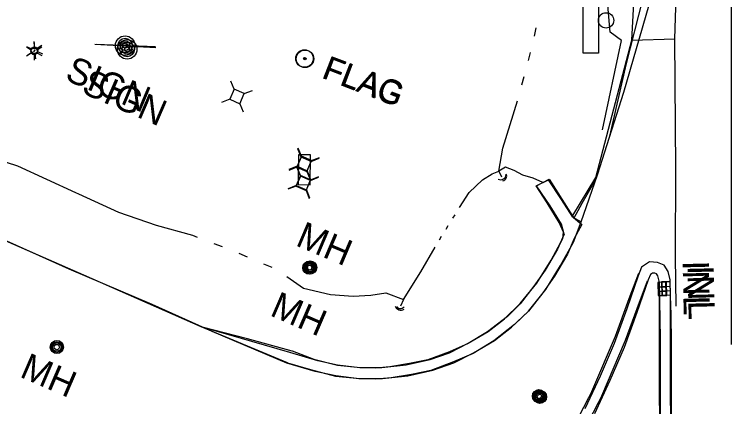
# Model space of a CAD drawing. Extents: x 588843 to 2552415, y 180129 to 269402.
# Drawn here: x 593696.8 to 593860.8, y 185673.4 to 185762.9 of the extents above; entities that cross this region are included whole.
import ezdxf

# ---------------------------------------------------------------- set-up
doc = ezdxf.new("R2010")
doc.units = 0
for name, color, linetype in [('Default', 7, 'Continuous'), ('E_AREA', 7, 'Continuous'), ('E_DRN', 7, 'Continuous'), ('E_DRN_Text', 7, 'Continuous'), ('E_LTG', 7, 'Continuous'), ('E_MISCPROP', 7, 'Continuous'), ('E_RDWY', 7, 'Continuous'), ('E_RDWY_AsphConc', 7, 'Continuous'), ('E_RDWY_C_and_G', 7, 'Continuous'), ('E_RDWY_Gravel', 7, 'Continuous'), ('E_RDWY_PavtEdge', 7, 'Continuous'), ('E_SGN', 7, 'Continuous'), ('E_SGN_Text', 7, 'Continuous'), ('E_UTL_AG_Bold', 7, 'Continuous'), ('E_UTL_MH', 7, 'Continuous'), ('E_UTL_MH_Text', 7, 'Continuous'), ('E_WTR_P', 7, 'Continuous')]:
    doc.layers.add(name, color=color, linetype=linetype)

# ---------------------------------------------------------------- blocks, each defined once
blk = doc.blocks.new('LPOL')
at = {"layer": 'Default'}
for p, q in [((-0.75, 1.3), (-2, 3.46)), ((0.75, 1.3), (2, 3.46)), ((-4, 0), (-1.5, 0)), ((1.5, 0), (4, 0)), ((-2, -3.46), (-0.75, -1.3)), ((2, -3.46), (0.75, -1.3))]:
    blk.add_line(p, q, dxfattribs=at)
for radius in [1.5, 1.5, 1.5, 0.125]:
    blk.add_circle((0, 0), radius, dxfattribs=at)
blk = doc.blocks.new('POLE')
at = {"layer": 'Default'}
for radius in [4.46, 3.35, 2.23, 1.12]:
    blk.add_circle((0, 0), radius, dxfattribs=at)
blk = doc.blocks.new('SIGN')
at = {"layer": 'Default'}
blk.add_text('SIGN', height=12, dxfattribs=at).set_placement((-18.55, -6))
blk = doc.blocks.new('PED')
at = {"layer": 'Default'}
for p, q in [((-2.5, 2.5), (-5.33, 5.33)), ((2.5, 2.5), (5.33, 5.33)), ((-2.5, -2.5), (-5.33, -5.33)), ((2.5, -2.5), (5.33, -5.33))]:
    blk.add_line(p, q, dxfattribs=at)
blk.add_lwpolyline([(-2.5, -2.5), (2.5, -2.5), (2.5, 2.5), (-2.5, 2.5)], close=True, dxfattribs=at)
blk = doc.blocks.new('MHO')
at = {"layer": 'Default'}
for centre, radius in [((0.08, -0.12), 3), ((0.08, -0.12), 2.43), ((0.07, -0.15), 1.94), ((0.02, -0.16), 1.21)]:
    blk.add_circle(centre, radius, dxfattribs=at)
blk = doc.blocks.new('MHT')
at = {"layer": 'E_UTL_MH_Text'}
blk.add_text('MH', height=12, dxfattribs=at).set_placement((-9.81, -6))
blk = doc.blocks.new('FPOL')
at = {"layer": 'Default'}
for radius in [4, 0.5]:
    blk.add_circle((0, 0), radius, dxfattribs=at)
blk.add_text('FLAG', height=10.8, dxfattribs=at).set_placement((10, -5.4))
blk = doc.blocks.new('INLO')
at = {"layer": 'E_DRN'}
for p, q in [((2, -4), (2, 0)), ((4, -4), (4, 0)), ((6, -2), (0, -2))]:
    blk.add_line(p, q, dxfattribs=at)
blk.add_lwpolyline([(0, -4), (6, -4), (6, 0), (0, 0), (0, -4)], close=True, dxfattribs=at)
blk = doc.blocks.new('INLT_24')
at = {"layer": 'E_DRN_Text'}
blk.add_text('INL', height=12, dxfattribs=at).set_placement((-11.03, -6))
blk = doc.blocks.new('CULV2')
at = {"layer": 'E_DRN'}
blk.add_arc((19.7, 14.8), 24.6, 216.8699, 323.1301, dxfattribs=at)
blk = doc.blocks.new('SGN_1')
at = {"layer": 'Default'}
blk.add_lwpolyline([(-3.5, -15), (-10.5, -15), (-10.5, 15), (-3.5, 15)], close=True, dxfattribs=at)
blk.add_circle((0, 0), 3.5, dxfattribs=at)
blk = doc.blocks.new('CULV2_4')
at = {"layer": 'E_DRN'}
blk.add_arc((64.6, 48.4), 80.7, 216.8699, 323.1301, dxfattribs=at)
blk = doc.blocks.new('INLO_3')
at = {"layer": 'E_DRN'}
for p, q in [((6.6, -13.1), (6.6, 0)), ((13.1, -13.1), (13.1, 0)), ((19.7, -6.6), (0, -6.6))]:
    blk.add_line(p, q, dxfattribs=at)
blk.add_lwpolyline([(0, -13.1), (19.7, -13.1), (19.7, 0), (0, 0)], close=True, dxfattribs=at)
blk = doc.blocks.new('INLT_44')
at = {"layer": 'E_DRN_Text'}
blk.add_text('INL', height=39.37, dxfattribs=at).set_placement((-36.2, -19.7))
blk = doc.blocks.new('MHO_3')
at = {"layer": 'E_UTL_MH'}
for centre, radius in [((0.3, -0.4), 9.84), ((0.3, -0.4), 7.98), ((0.2, -0.5), 6.35), ((0.1, -0.5), 3.97)]:
    blk.add_circle(centre, radius, dxfattribs=at)
blk = doc.blocks.new('PED_3')
at = {"layer": 'E_UTL_AG_Bold'}
for p, q in [((-8.2, 8.2), (-17.5, 17.5)), ((8.2, 8.2), (17.5, 17.5)), ((-8.2, -8.2), (-17.5, -17.5)), ((8.2, -8.2), (17.5, -17.5))]:
    blk.add_line(p, q, dxfattribs=at)
blk.add_lwpolyline([(-8.2, -8.2), (8.2, -8.2), (8.2, 8.2), (-8.2, 8.2)], close=True, dxfattribs=at)
blk = doc.blocks.new('LPOL_4')
at = {"layer": 'E_LTG'}
for p, q in [((-2.5, 4.3), (-6.6, 11.4)), ((2.5, 4.3), (6.6, 11.4)), ((-13.1, 0), (-4.9, 0)), ((4.9, 0), (13.1, 0)), ((-6.6, -11.4), (-2.5, -4.3)), ((6.6, -11.4), (2.5, -4.3))]:
    blk.add_line(p, q, dxfattribs=at)
for radius in [4.92, 4.92, 4.92, 0.41]:
    blk.add_circle((0, 0), radius, dxfattribs=at)
blk = doc.blocks.new('POLE_3')
at = {"layer": 'E_MISCPROP'}
for radius in [14.6, 11, 7.32, 3.66]:
    blk.add_circle((0, 0), radius, dxfattribs=at)
blk = doc.blocks.new('FPOL_2')
at = {"layer": 'E_MISCPROP'}
for radius in [13.1, 1.64]:
    blk.add_circle((0, 0), radius, dxfattribs=at)
blk.add_text('FLAG', height=35.43, dxfattribs=at).set_placement((32.8, -17.7))
blk = doc.blocks.new('SIGN_3')
at = {"layer": 'E_SGN'}
blk.add_text('SIGN', height=39.37, dxfattribs=at).set_placement((-56.1, -19.7))
blk = doc.blocks.new('MHT_1_1')
at = {"layer": 'E_UTL_MH'}
blk.add_text('MH', height=39.37, dxfattribs=at).set_placement((-32.2, -19.7))

msp = doc.modelspace()

# ---------------------------------------------------------------- linework, layer by layer
at = {"layer": 'E_AREA'}
msp.add_lwpolyline([(593764.45, 185724.01), (593764.53, 185730.85), (593761.77, 185730.88), (593761.68, 185724.05)], close=True, dxfattribs=at)
at = {"layer": 'E_RDWY'}
for points in [[(593759.1, 185683.31), (593742.04, 185690.53), (593728.3, 185696.69), (593709.33, 185704.73), (593695.77, 185710.83), (593682.84, 185716.47), (593670.2, 185721.87), (593658.17, 185727.03), (593647.4, 185731.86), (593631.92, 185738.54), (593621.67, 185743), (593610.57, 185747.71), (593598.94, 185752.59), (593585.45, 185758.54), (593573.64, 185763.64), (593561.33, 185768.89), (593544.91, 185776.17), (593525.62, 185787.49)], [(593759.23, 185683.39), (593739.55, 185691.58), (593712.69, 185703.4), (593684.94, 185715.45), (593651.85, 185729.61), (593625.47, 185740.91), (593596.7, 185753.38), (593563.11, 185767.85), (593537.55, 185779.12), (593525.28, 185784.5)], [(593824.44, 185716.62), (593826.41, 185715.58), (593830.12, 185726.28), (593836.13, 185745.12), (593841.89, 185765.08)], [(593822.49, 185712.74), (593821.85, 185714.99), (593819.27, 185719.19), (593816.17, 185723.77), (593819.09, 185725.3), (593823.93, 185717.6), (593824.62, 185716.54), (593826.52, 185714.96), (593824.78, 185711.76)]]:
    msp.add_lwpolyline(points, dxfattribs=at)
at = {"layer": 'E_RDWY_AsphConc'}
for points in [[(593837.95, 185757.04), (593839.67, 185789.55), (593841.84, 185838.91), (593843.28, 185888.97), (593844.22, 185921.24), (593844.22, 185921.24), (593844.83, 185937.64), (593844.83, 185937.64), (593846.87, 185985.61), (593846.87, 185985.61), (593846.9, 185986.19), (593846.9, 185986.19), (593847.86, 186002.92), (593847.86, 186002.92), (593849.8, 186035.84), (593849.8, 186035.84), (593849.89, 186037.26), (593849.89, 186037.26), (593852.73, 186084.79), (593853.52, 186097.05), (593853.52, 186097.05), (593855.43, 186124.4), (593855.43, 186124.4)], [(593824.49, 185717), (593829.72, 185725.66), (593837.95, 185757.04), (593847.81, 185757.3)], [(593848.12, 185696.34), (593847.9, 185707.68), (593848.04, 185727.75), (593847.81, 185757.3)]]:
    msp.add_lwpolyline(points, dxfattribs=at)
at = {"layer": 'E_RDWY_C_and_G'}
for points in [[(593760.34, 185686.11), (593765.28, 185684.2), (593770.66, 185682.82), (593775.96, 185682.27), (593780.78, 185682.27), (593786.34, 185682.9), (593791.83, 185684.14), (593796.26, 185685.64), (593800.52, 185687.87), (593805.13, 185690.54), (593808.84, 185693.44), (593812.46, 185696.9), (593816.26, 185701.53), (593819.5, 185706.83), (593822.22, 185711.78), (593822.31, 185713.22), (593821.35, 185715.39), (593818.57, 185719.91), (593816.06, 185723.79), (593818.93, 185725.13)], [(593824.44, 185716.62), (593821.72, 185720.91), (593818.93, 185725.13)], [(593759.23, 185683.39), (593764.51, 185681.81), (593770.22, 185680.35), (593775.83, 185679.77), (593780.93, 185679.77), (593786.76, 185680.43), (593792.5, 185681.73), (593797.24, 185683.34), (593801.73, 185685.68), (593806.53, 185688.46), (593810.47, 185691.54), (593814.3, 185695.2), (593818.3, 185700.08), (593821.66, 185705.57), (593824.6, 185710.93), (593826.41, 185715.58)], [(593824.78, 185711.76), (593823.23, 185708.14), (593820.26, 185703.13), (593817.58, 185699.37), (593814.3, 185695.19), (593811.16, 185692.09), (593806.43, 185688.41), (593801.7, 185685.52), (593797.2, 185683.56), (593792.03, 185681.65), (593787.58, 185680.72), (593782.96, 185679.95), (593779.42, 185679.65), (593775.59, 185679.72), (593770.3, 185680.39), (593765.59, 185681.38), (593759.07, 185683.29)], [(593822.49, 185712.74), (593821, 185709.28), (593818.16, 185704.49), (593815.58, 185700.87), (593812.43, 185696.86), (593809.51, 185693.98), (593805, 185690.47), (593800.54, 185687.75), (593796.27, 185685.88), (593791.34, 185684.06), (593787.12, 185683.18), (593782.64, 185682.44), (593779.34, 185682.15), (593775.77, 185682.22), (593770.71, 185682.86), (593766.2, 185683.81), (593759.77, 185685.69)], [(593846.84, 185669.38), (593846.76, 185677.79), (593846.8, 185698.58), (593846.71, 185702.32), (593846.24, 185704.19), (593845.32, 185705.67), (593843.83, 185706.28), (593841.99, 185706.42), (593840.16, 185705.18), (593839.38, 185703.21), (593836.78, 185695.67), (593833.88, 185687.81), (593830.68, 185680.34), (593827.19, 185672.86)], [(593846.76, 185697.53), (593846.93, 185689.06), (593846.95, 185664.12), (593846.94, 185653.04), (593846.28, 185651.51), (593845.16, 185650.27), (593843.9, 185649.34), (593842.62, 185648.72), (593840.87, 185648.28), (593827.3, 185652.15), (593823.42, 185653.26), (593822.24, 185653.8), (593820.79, 185655.02), (593820.26, 185656.61), (593819.9, 185658.3), (593820.18, 185660.06), (593824.69, 185668.82), (593828.15, 185675.47), (593828.79, 185676.8), (593834.19, 185689.48), (593837.34, 185698.09), (593839.55, 185703.83)], [(593844.34, 185669.38), (593844.26, 185677.79), (593844.3, 185698.56), (593844.22, 185701.98), (593843.91, 185703.21), (593843.62, 185703.67), (593843.25, 185703.82), (593842.67, 185703.86), (593842.2, 185703.54), (593841.72, 185702.34), (593839.13, 185694.83), (593836.2, 185686.89), (593832.96, 185679.32), (593829.43, 185671.76)], [(593844.17, 185701.71), (593844.43, 185689.03), (593844.45, 185664.12), (593844.44, 185653.56), (593844.15, 185652.88), (593843.48, 185652.13), (593842.6, 185651.49), (593841.76, 185651.08), (593840.92, 185650.87), (593827.99, 185654.55), (593824.29, 185655.61), (593823.58, 185655.93), (593822.94, 185656.48), (593822.67, 185657.27), (593822.44, 185658.36), (593822.59, 185659.27), (593826.92, 185667.67), (593830.37, 185674.32), (593831.08, 185675.82), (593836.51, 185688.56), (593839.68, 185697.21), (593841.55, 185702.08)]]:
    msp.add_lwpolyline(points, dxfattribs=at)
at = {"layer": 'E_RDWY_Gravel'}
msp.add_line((593759.77, 185685.69), (593740.08, 185691.41), dxfattribs=at)
for points in [[(593831.22, 185736.59), (593835.61, 185756.96), (593833.01, 185758.89), (593830.96, 185782.65), (593830.12, 185791.32), (593830.79, 185838.58), (593829.63, 185872.43), (593828.76, 185889.27)], [(593832.93, 185735.09), (593836.71, 185751.67), (593840.45, 185766.4), (593843.33, 185777.36), (593845.2, 185783.93), (593847.16, 185791.33)], [(593824.79, 185716.44), (593826.62, 185719.82), (593829.81, 185725.4)], [(593760.31, 185686.02), (593750.11, 185688.84), (593739.77, 185691.49)]]:
    msp.add_lwpolyline(points, dxfattribs=at)
at = {"layer": 'E_RDWY_PavtEdge'}
for points in [[(593847.81, 185757.3), (593848.76, 185788.45), (593849.81, 185838.52), (593850.55, 185888.9), (593851.07, 185921.17), (593851.07, 185921.17), (593851.53, 185937.39), (593851.53, 185937.39), (593853.26, 185984.29), (593853.26, 185984.29), (593853.32, 185985.9), (593853.32, 185985.9), (593854.89, 186023.96), (593854.89, 186023.96), (593855.46, 186035.86), (593855.46, 186035.86), (593855.74, 186040.82), (593855.74, 186040.82), (593858.37, 186084.45), (593858.37, 186084.45), (593859.08, 186096.87), (593859.08, 186096.87), (593860.55, 186123.99), (593860.55, 186123.99)], [(593860.7, 185687.52), (593860.77, 185701.49), (593860.73, 185757.58), (593860.74, 185788.64)]]:
    msp.add_lwpolyline(points, dxfattribs=at)
at = {"layer": 'E_SGN'}
msp.add_line((593715.24, 185756.14), (593729.17, 185755.39), dxfattribs=at)
msp.add_lwpolyline([(593715.5, 185756.09), (593729.08, 185755.61)], dxfattribs=at)
at = {"layer": 'E_WTR_P'}
for points in [[(593815.71, 185757.96), (593816.11, 185759.83)], [(593814.34, 185752.4), (593814.82, 185754.24)], [(593812.84, 185746.86), (593813.35, 185748.71)], [(593817.6, 185724.55), (593815.37, 185725.51), (593813.06, 185726.19), (593811.04, 185727.3), (593809.05, 185728.04), (593807.56, 185727.13), (593808.45, 185732.4), (593811.83, 185743.18)], [(593683.23, 185733.06), (593685.44, 185732.21), (593697.5, 185728.35), (593710.8, 185722.23)], [(593798.57, 185718.81), (593800.8, 185722.25), (593803.8, 185725.12), (593806, 185726.52), (593807.56, 185727.13), (593808.2, 185725.82)], [(593710.8, 185722.23), (593711.48, 185721.92), (593720.63, 185717.74), (593729.23, 185714.79), (593737.51, 185712.51), (593738.6, 185712.09)], [(593797.03, 185716.37), (593797.54, 185717.18)], [(593795.49, 185713.92), (593796, 185714.74)], [(593793.99, 185711.45), (593794.47, 185712.28)], [(593742.42, 185710.62), (593744.33, 185709.89)], [(593785.75, 185697.83), (593789.73, 185704.13), (593793.02, 185709.78)], [(593748.13, 185708.39), (593750.01, 185707.59)], [(593753.78, 185706), (593755.66, 185705.2)], [(593759.13, 185703.06), (593762.92, 185700.41), (593769.04, 185698.96), (593774.24, 185698.56), (593778.27, 185698.85), (593781.69, 185699.33), (593785.75, 185697.83), (593785.04, 185696.29)]]:
    msp.add_lwpolyline(points, dxfattribs=at)

# ---------------------------------------------------------------- block references
at = {"layer": 'E_DRN'}
for name, p, xscale, yscale, rotation in [('CULV2_4', (593807.43, 185725.28), 0.016407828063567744, 0.016407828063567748, 30.421582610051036), ('CULV2', (593808.48, 185724.93), 0.043553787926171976, 0.04355378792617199, 63.12337477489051), ('INLO', (593845.9, 185701.75), 0.5, 0.4999999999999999, -88.75564168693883), ('INLO_3', (593846.72, 185701.88), 0.1524003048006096, 0.1524003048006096, -88.62500351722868), ('CULV2_4', (593783.88, 185696.31), 0.016475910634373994, 0.016475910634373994, -19.028589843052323), ('CULV2', (593784.16, 185696.22), 0.04360226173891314, 0.04360226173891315, -1.1666714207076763)]:
    msp.add_blockref(name, p, dxfattribs=dict(at, xscale=xscale, yscale=yscale, rotation=rotation))
at = {"layer": 'E_DRN_Text'}
for name, p, xscale, yscale, rotation in [('INLT_24', (593852.67, 185701.21), 0.4999999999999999, 0.5, -88.66504860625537), ('INLT_44', (593853.8, 185700.11), 0.1524003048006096, 0.1524003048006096, -88.62500351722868)]:
    msp.add_blockref(name, p, dxfattribs=dict(at, xscale=xscale, yscale=yscale, rotation=rotation))
at = {"layer": 'E_LTG'}
for name, p, xscale, yscale, rotation in [('LPOL_4', (593701.44, 185754.75), 0.1524003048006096, 0.15240030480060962, -84.36014555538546), ('LPOL', (593701.33, 185754.48), 0.5000000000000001, 0.5, -89.67337617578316)]:
    msp.add_blockref(name, p, dxfattribs=dict(at, xscale=xscale, yscale=yscale, rotation=rotation))
at = {"layer": 'E_MISCPROP'}
for name, p, xscale, yscale, rotation in [('POLE', (593722.13, 185755.78), 0.5, 0.5, -112.98358720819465), ('POLE_3', (593722.59, 185754.93), 0.1524003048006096, 0.15240030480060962, -84.36014555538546), ('FPOL', (593763.13, 185752.83), 0.5, 0.4999999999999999, -21.229744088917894), ('FPOL_2', (593763.25, 185752.78), 0.1524003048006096, 0.15240030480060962, -20.59240922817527)]:
    msp.add_blockref(name, p, dxfattribs=dict(at, xscale=xscale, yscale=yscale, rotation=rotation))
at = {"layer": 'E_SGN', "xscale": 0.5, "yscale": 0.5}
msp.add_blockref('SGN_1', (593832.06, 185761.55), dxfattribs=at)
at = {"layer": 'E_SGN_Text'}
for name, p, xscale, yscale, rotation in [('SIGN', (593717.83, 185747.2), 0.4999999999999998, 0.4999999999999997, -22.955132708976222), ('SIGN_3', (593720.92, 185744.45), 0.15240030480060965, 0.15240030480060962, -23.45649658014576)]:
    msp.add_blockref(name, p, dxfattribs=dict(at, xscale=xscale, yscale=yscale, rotation=rotation))
at = {"layer": 'E_UTL_AG_Bold'}
for name, p, xscale, yscale, rotation in [('PED_3', (593747.7, 185744.17), 0.1524003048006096, 0.1524003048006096, 156.5196793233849), ('PED', (593763.01, 185728.69), 0.4999999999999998, 0.4999999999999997, -22.955132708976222), ('PED_3', (593763.08, 185728.88), 0.1524003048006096, 0.1524003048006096, 156.5196793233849), ('PED_3', (593762.85, 185724.36), 0.1524003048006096, 0.1524003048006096, 156.5196793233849), ('PED', (593762.89, 185724.51), 0.4999999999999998, 0.4999999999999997, -22.955132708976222)]:
    msp.add_blockref(name, p, dxfattribs=dict(at, xscale=xscale, yscale=yscale, rotation=rotation))
at = {"layer": 'E_UTL_MH'}
for name, p, xscale, yscale, rotation in [('MHO_3', (593764.22, 185705.16), 0.15240030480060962, 0.1524003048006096, -21.34473352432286), ('MHO', (593764.44, 185705.2), 0.4999999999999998, 0.4999999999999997, -22.955132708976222), ('MHT_1_1', (593760.68, 185695.08), 0.1524003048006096, 0.15240030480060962, -23.403919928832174), ('MHO', (593706.52, 185687.05), 0.49999999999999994, 0.5000000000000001, -23.33669759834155), ('MHO_3', (593816.94, 185675.67), 0.15240030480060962, 0.1524003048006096, -24.71044485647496), ('MHO', (593816.79, 185675.82), 0.4999999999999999, 0.49999999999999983, -89.47457921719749)]:
    msp.add_blockref(name, p, dxfattribs=dict(at, xscale=xscale, yscale=yscale, rotation=rotation))
at = {"layer": 'E_UTL_MH_Text'}
for p, xscale, yscale, rotation in [((593766.54, 185711.1), 0.4999999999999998, 0.4999999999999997, -22.955132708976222), ((593703.49, 185681.07), 0.49999999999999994, 0.5000000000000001, -23.33669759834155)]:
    msp.add_blockref('MHT', p, dxfattribs=dict(at, xscale=xscale, yscale=yscale, rotation=rotation))

doc.saveas('drawing.dxf')
